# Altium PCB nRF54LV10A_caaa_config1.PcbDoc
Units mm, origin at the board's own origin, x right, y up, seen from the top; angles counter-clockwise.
Board outline 10.2 x 7.5 mm, 6 copper layers (Top Layer, Mid-Layer 1, Mid-Layer 2, Mid-Layer 3, Mid-Layer 4, Bottom Layer), stack 1.59 mm thick; 21 components, 30 nets, 71 pads, 43 vias.
Unrouted connection lines stored in the file: 14.
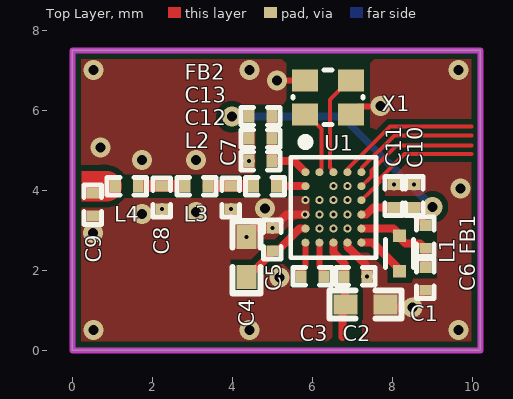
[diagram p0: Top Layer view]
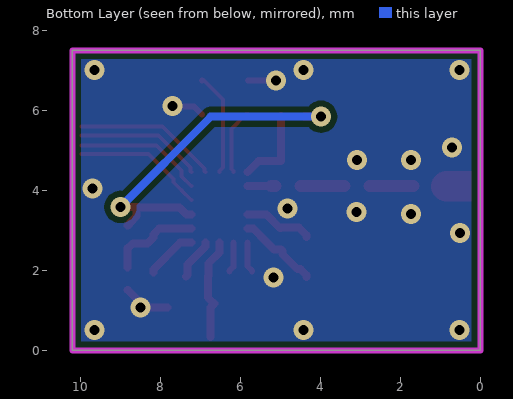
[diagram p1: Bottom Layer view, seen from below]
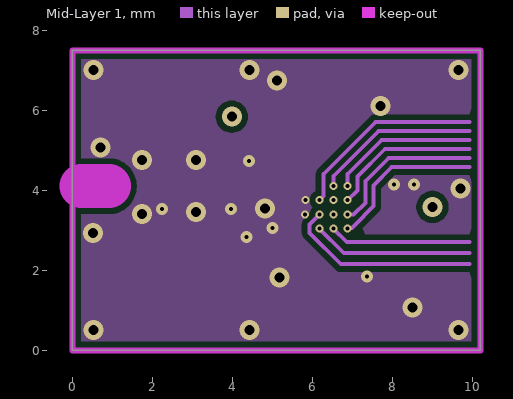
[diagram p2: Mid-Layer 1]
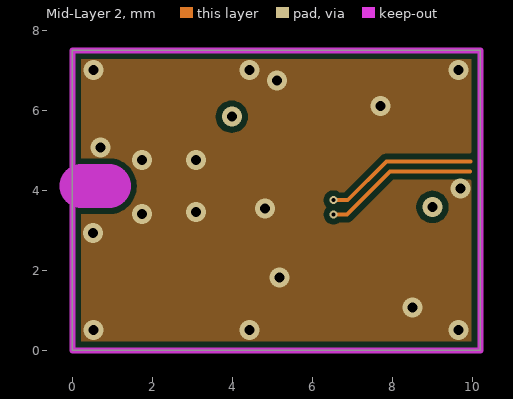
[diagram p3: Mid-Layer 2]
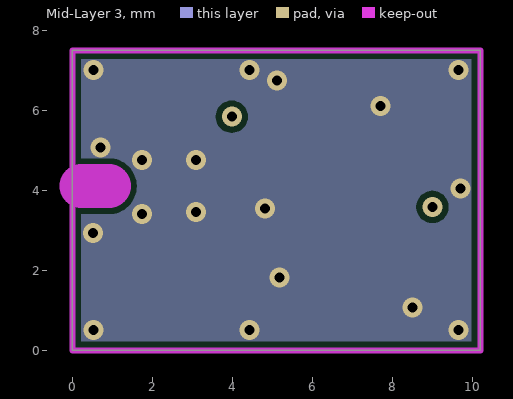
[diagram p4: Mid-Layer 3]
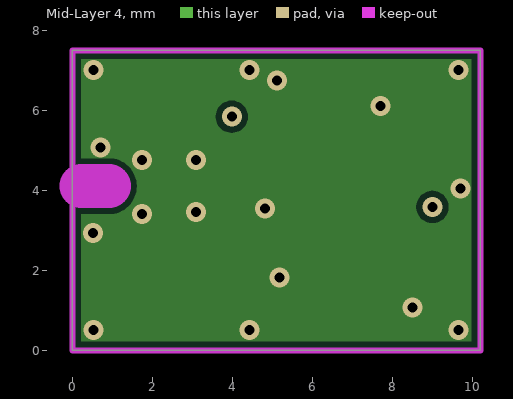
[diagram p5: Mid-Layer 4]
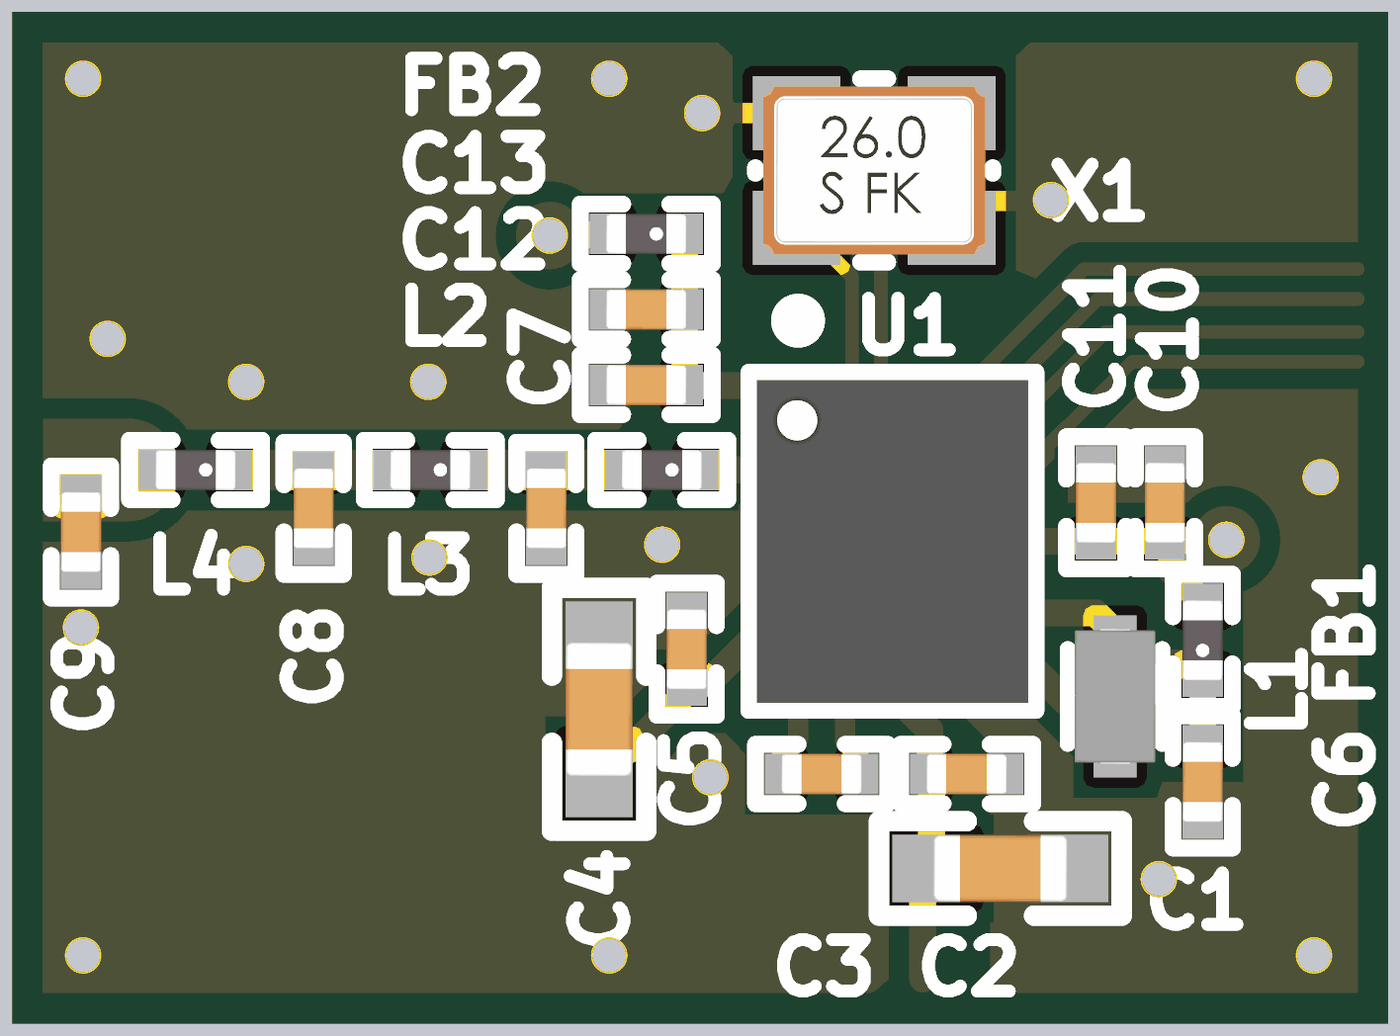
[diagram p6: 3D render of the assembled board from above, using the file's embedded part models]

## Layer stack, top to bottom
Top Solder: solder mask 0.0254, SM-003, Dk 4
Top Layer: signal copper 0.035
Dielectric 1: prepreg 0.07, Dk 4.2
Mid-Layer 1: signal copper 0.035
Dielectric 4: prepreg 0.07, PP-006, Dk 4.1
Mid-Layer 2: signal copper 0.035
Dielectric 3: core 1.1, Dk 4.6
Mid-Layer 3: signal copper 0.035
Dielectric 5: prepreg 0.07, PP-006, Dk 4.1
Mid-Layer 4: signal copper 0.035
Dielectric 2: prepreg 0.07, Dk 4.2
Bottom Layer: signal copper 0.035
Board Layer Stack Bottom Solder: solder mask 0.0254, SM-003, Dk 4

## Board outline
0,0 0,7.5 10.2,7.5 10.2,0

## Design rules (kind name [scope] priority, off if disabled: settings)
Clearance Polygon_RF [InNet('GND') vs InNet('RF')] p1: gap=0.15 ignorepadtopadclearanceinfootprint=FALSE
Clearance Clearance_Poly [(InNamedPolygon('Top_Layer-GND')) or (InNamedPolygon('Bottom_Layer-GND')) or (InNamedPolygon('Mid_Layer1-GND')) or (InNamedPolygon('Mid_Layer2-GND'))] p2: gap=0.15 ignorepadtopadclearanceinfootprint=FALSE
Clearance Clearance_nRF54 [WithinRoom('nRF54')] p3: gap=0.1 ignorepadtopadclearanceinfootprint=FALSE except(0: Arc-Hole Track-Hole SMDPad-Hole THPad-Hole Via-Hole Fill-Hole Poly-Hole Region-Hole Text-Hole; 0.15: Arc-Poly Arc-Region Track-Poly Track-Region SMDPad-Poly SMDPad-Region THPad-Poly THPad-Region Via-Poly Via-Region Fill-Poly Fill-Region Poly-Poly Poly-Region Region-Region)
Clearance [All] p4: gap=0.15 ignorepadtopadclearanceinfootprint=FALSE except(0: Arc-Hole Track-Hole SMDPad-Hole THPad-Hole Via-Hole Fill-Hole Poly-Hole Region-Hole Text-Hole)
ComponentClearance [All] p1 off: gap=0.254 collisioncheckmode=3 verticalgap=0.254 showdistances=FALSE
FabricationTestPointUsage TestPointUsage [All] p1: valid=0 allowmultiple=FALSE
FabricationTestpoint Testpoint [All] p1: side=3 testpointundercomponent=TRUE minsize=1.016 maxsize=2.54 preferedsize=1.524 minholesize=0 maxholesize=1.016 preferedholesize=0.813 testpointgrid=0.025 allowsidetop=TRUE allowsidebottom=TRUE usegrid=TRUE gridtolerance=0
Height [All] p1 off: minheight=0 maxheight=25.4 prefheight=12.7
HoleSize [All] p1: absolutevalues=TRUE maxlimit=4 minlimit=0.1 maxpercent=80.000 minpercent=20.000
HoleToHoleClearance [IsThruVia vs IsThruVia] p1: gap=0.36 allowstackedmicrovias=TRUE
MinimumAnnularRing [All] p1 off: minimumring=0.152
PlaneClearance [All] p1: clearance=0.2
PolygonConnect Component_direct [InComponent('C1') or InComponent('C2') or InComponent('C4')  or InComponent('C5') or InComponent('C6') or InComponent('C7') or InComponent('C8') or InComponent('C9') or InComponent('C10') or InComponent('C11') or InComponent('C12') or InComponent('C13') or InComponent('L4')   or InComponent('U1')] p1: connectstyle=Direct reliefconductorwidth=0.254 reliefentries=4 polygonreliefangle="90 Angle" airgapwidth=0.254
PolygonConnect "Via GND" [isVia and innet('GND')] p2: connectstyle=Direct reliefconductorwidth=0.254 reliefentries=4 polygonreliefangle="90 Angle" airgapwidth=0.254
PolygonConnect [All] p3: thpad.connectstyle=Relief thpad.reliefconductorwidth=0.254 thpad.reliefentries=4 thpad.polygonreliefangle="90 Angle" thpad.airgapwidth=0.15 smdpad.connectstyle=Relief smdpad.reliefconductorwidth=0.25 smdpad.reliefentries=4 smdpad.polygonreliefangle="90 Angle" smdpad.airgapwidth=0.15 via.connectstyle=Direct via.reliefconductorwidth=0.254 via.reliefentries=4 via.polygonreliefangle="90 Angle" via.airgapwidth=0.25
RoomDefinition nRF54 [False vs False] p1: confinementstyle=ConfineIn formatcopy=TRUE lockcomponents=FALSE outline 5.334,5.95 10.1,5.95 10.1,1.975 5.334,1.975
RoutingVias [All] p1: holewidth=0.2 width=0.4 viastyle="Through Hole" minholewidth=0.1 minwidth=0.2 maxholewidth=1 maxwidth=2 useviatemplates=TRUE viatemplateguid#1={5C31B0A3-9274-4A8C-AAD4-E2B2741298D6} viatemplateguid#2={C8464F81-CA02-4378-B3B7-72CF0372187D} viatemplatename#1=v20h10m0 viatemplatename#2=v30h10m0
SilkToSolderMaskClearance SilkscreenOverComponentPads [IsPad] p1: minsilkscreentomaskgap=0.254 clearancetoexposedcopper=TRUE
SolderMaskExpansion SolderMaskExpansion_via [IsVia] p1: expansion=0.102 istentingtop=TRUE
SolderMaskExpansion [All] p2: expansion=0.076 istentingtop=FALSE
Width [All] p1: maxlimit=3 minlimit=0.09 preferedwidth=0.15
22 further rules are at their usual default settings.

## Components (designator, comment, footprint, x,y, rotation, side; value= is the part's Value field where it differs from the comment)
C1 "10µF" CAPC1005X04L 7.325,1.15 r180 top
C2 "100nF" CAPC0603X03L_C#1 7.075,1.85 r0 top
C3 "1.0µF" CAPC0603X03L_C#2 6,1.85 r180 top
C4 "10µF" CAPC1005X04L 4.35,2.33 r270 top
C5 "100nF" CAPC0603X03L_C#1 5,2.775 r90 top
C6 "4.7µF" CAPC0603X03L_C#3 8.825,1.791 r90 top
C7 "1.2pF" CAPC0603X03L_C#3 3.959,3.82 r90 top
C8 "0.8pF" CAPC0603X03L_C#3 2.234,3.82 r90 top
C9 "0.3pF" CAPC0603X03L_C#3 0.509,3.644 r90 top
C10 "2.2µF" CAPC0603X03L_C#1 8.545,3.861 r90 top
C11 "10nF" CAPC0603X03L_C#3 8.035,3.861 r270 top
C12 "18pF" CAPC0603X03L_C#3 4.7,4.735 r0 top
C13 "2.2µF" CAPC0603X03L_C#1 4.7,5.295 r180 top
FB1 "120R/0.2A" INDC0603X03L_C 8.825,2.841 r90 top
FB2 "120R/0.2A" INDC0603X03L_C 4.7,5.855 r180 top
L1 "4.7µH" INDDFN10X06X08L31X32L 8.175,2.425 r270 top
L2 "2.7nH" INDC0603X03L_C 4.815,4.105 r180 top
L3 "6.2nH" INDC0603X03L_C 3.099,4.105 r180 top
L4 "4.3nH" INDC0603X03L_C 1.359,4.105 r180 top
U1 "nRF54LV10A-CAAA" BGA29CP35_5X6_239X201X45B20 6.525,3.575 r0 top
X1 "32MHz" BT-XTAL_1612 6.389,6.325 r0 top

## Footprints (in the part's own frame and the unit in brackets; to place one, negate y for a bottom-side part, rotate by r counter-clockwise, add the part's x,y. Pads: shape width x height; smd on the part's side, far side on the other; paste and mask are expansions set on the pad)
BGA29CP35_5X6_239X201X45B20 [mm] "Ball Grid Array (BGA) Collapsing, 0.35 mm pitch, rect.; 29 pin, 2.393 mm L X 2.012 mm W X 0.45 mm H body"
  round 0.2 smd paste+0 mask+0.025: A1(-0.7,0.88) A2(-0.35,0.88) A3(0,0.88) A4(0.35,0.88) A5(0.7,0.88) B1(-0.7,0.53) B3(0,0.53) B4(0.35,0.53) B5(0.7,0.53) C1(-0.7,0.18) C2(-0.35,0.18) C3(0,0.18) C4(0.35,0.18) C5(0.7,0.18) D1(-0.7,-0.18) D2(-0.35,-0.18) D3(0,-0.18) D4(0.35,-0.18) D5(0.7,-0.18) E1(-0.7,-0.53) E2(-0.35,-0.53) E3(0,-0.53) E4(0.35,-0.53) E5(0.7,-0.53) F1(-0.7,-0.88) F2(-0.35,-0.88) F3(0,-0.88) F4(0.35,-0.88) F5(0.7,-0.88)
  silkscreen extent -1.07,-1.26 1.07,1.74, body extent -1.01,-1.2 1.01,1.2, height 0.45
BT-XTAL_1612 [mm] "Crystal 1.6 x 1.2 mm"
  rect 0.65x0.55 smd: 1(-0.575,-0.425) 2(0.575,-0.425) 3(0.575,0.425) 4(-0.575,0.425)
  silkscreen extent -0.88,-0.68 0.88,0.68, body extent -0.83,-0.63 0.83,0.63, height 0.41
CAPC0603X03L_C#1 [mm] "Chip Capacitor, 2-Leads, Body 0.6x0.3mm, IPC High Density"
  rect 0.27x0.3 smd mask+0.05: 1(-0.285,0)
  rect 0.27x0.3 smd mask+0: 2(0.285,0)
  silkscreen extent -0.49,-0.22 0.49,0.22, body extent -0.3,-0.15 0.3,0.15, height 0.3
CAPC0603X03L_C#2 [mm] "Chip Capacitor, 2-Leads, Body 0.6x0.3mm, IPC High Density"
  rect 0.27x0.3 smd mask+0.05: 1(-0.285,0) 2(0.285,0)
  silkscreen extent -0.49,-0.22 0.49,0.22, body extent -0.3,-0.15 0.3,0.15, height 0.3
CAPC0603X03L_C#3 [mm] "Chip Capacitor, 2-Leads, Body 0.6x0.3mm, IPC High Density"
  rect 0.27x0.3 smd mask+0: 1(-0.285,0)
  rect 0.27x0.3 smd mask+0.05: 2(0.285,0)
  silkscreen extent -0.49,-0.22 0.49,0.22, body extent -0.3,-0.15 0.3,0.15, height 0.3
CAPC1005X04L [mm] "Chip Capacitor, 2-Leads, Body 1.0x0.5mm, IPC High Density"
  rect 0.6x0.5 smd mask+0: 1(-0.5,0)
  rect 0.6x0.5 smd: 2(0.5,0)
  silkscreen extent -0.9,-0.35 0.9,0.35, body extent -0.5,-0.25 0.5,0.25, height 0.5
INDC0603X03L_C [mm] "Chip Inductor, 2-Leads, Body 0.6x0.3mm, IPC High Density"
  rect 0.27x0.3 smd: 1(-0.285,0) 2(0.285,0)
  silkscreen extent -0.49,-0.22 0.49,0.22, body extent -0.3,-0.15 0.3,0.15, height 0.3
INDDFN10X06X08L31X32L [mm] "Inductor Dula Flat Package, 2-Leads, Body 1.0x0.6mm, IPC High Density"
  rect 0.31x0.32 smd mask+0.076: 1(-0.445,0) 2(0.445,0)
  silkscreen extent -0.35,-0.35 0.35,0.35, body extent -0.5,-0.3 0.5,0.3, height 0.79

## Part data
C1 C4: library part C0402-10µF-6.3V-X6S, "Capacitor, X6S, ±20%, 6.3V", Manufacturer=N.A., Part number NEMS=100200478
C2 C5: library part C0201-100n-10V-X7R, "Capacitor, X7R, ±10%, 100nF, 10V", Manufacturer=N.A., Part number NEMS=100200469
C3: library part C0201-1µ0-6.3V, "Capacitor, Ceramic, X5R, ±20%, 6.3V", Manufacturer=Murata, Manufacturer Part Number=GRM033R60J105MEA2D, Part number IPS=N.A., Part number NEMS=100200387, Supplier Part Number 1=490-7229-1-ND
C6: library part C0201-4.7µ-6V3-X5R-GRM035R60J475ME15J, "Capacitor, Ceramic, X5R, ±20%, 6.3V", Manufacturer=Murata, Manufacturer Part Number=GRM035R60J475ME15J, Part number IPS=N.A., Part number NEMS=100200685, Supplier Part Number 1=490-GRM035R60J475ME15JDKR-ND
C7: library part C0201-1.2p-HQ-Murata, "Capacitor, NP0, ±0.05pF, 50V", Manufacturer=Murata, Manufacturer Part Number=GJM0335C1H1R2WB01D, Part number IPS=N.A., Part number NEMS=100200457, Supplier Part Number 1=490-GJM0335C1H1R2WB01DCT-ND
C8: library part C0201-0.8p, "Capacitor, NP0, ±0.05pF, 50V", Manufacturer=Murata, Manufacturer Part Number=GJM0335C1HR80WB01, Part number IPS=80000001975, Part number NEMS=100200012, Part number Norautron=N.A.
C9: library part C0201-0.3p-50V-GRM0335C1HR30BA01, "Capacitor, C0G, ±0.1pF, 50V", Manufacturer=Murata, Manufacturer Part Number=GRM0335C1HR30BA01, Part number IPS=N.A., Part number NEMS=100200650, Supplier Part Number 1=490-6135-2-ND
C10 C13: library part C0201-2µ2-2.5V-X6T-GRM033D80E225ME47D, "Capacitor, Ceramic, 2.2µF 2.5V X6T 0201,±20%", Manufacturer=Murata, Manufacturer Part Number=GRM033D80E225ME47D, Part number IPS=N.A., Part number NEMS=100200527, Supplier Part Number 1=81-GRM033D80E225ME7D
C11: library part C0201-10n-6.3V-X7R, "Capacitor, X7R, 6.3V", Manufacturer=Murata, Manufacturer Part Number=GRM033R70J103KA01D, Part number IPS=N.A., Part number NEMS=100200407, Supplier Part Number 1=490-1262-1-ND
C12: library part C0201-18p, "Capacitor, C0G, ±5%, 25V", Manufacturer="Walsin Technology Corporation", Manufacturer Part Number=0201N180J250CT, Part number IPS=00000000862, Part number NEMS=100200035, Part number Norautron=26207023, Supplier Part Number 1=N.A.
FB1 FB2: library part FB0201-120R@100M-200mA-BLM03AG121SN1D, "Ferrite Bead, 120 Ohm @ 100MHz, 200mA, 500 mOhm Max", Manufacturer=Murata, Manufacturer Part Number=BLM03AG121SN1D, Part number IPS=N.A., Part number NEMS=100300419, Supplier Part Number 1=490-5622-1-ND
L1: library part L0402-4µ7-PLEA67BCA4R7M-1PT00, "Inductor, 300mA, ±20%, 1.08R", Manufacturer="TDK Corporation", Manufacturer Part Number=PLEA67BCA4R7M-1PT00, Part number IPS=N.A., Part number NEMS=100300441, Supplier Part Number 1=445-PLEA67BCA4R7M-1PT00TR-ND
L2: library part L0201-2n7-HQ-Murata, "Inductor, 600mA, ±0.1ｎH, 120mOhm", Manufacturer=Murata, Manufacturer Part Number=LQP03HQ2N7B02, Part number IPS=00000001753, Part number NEMS=100300214, Part number Norautron=N.A., Supplier Part Number 1=490-13909-1-ND
L3: library part L0201-6n2-HQ-Murata, "Inductor, 400mA, ±3%, 250mOhm", Manufacturer=Murata, Manufacturer Part Number=LQP03HQ6N2H02, Part number IPS=N.A., Part number NEMS=100300237, Supplier Part Number 1=490-13949-1-ND
L4: library part L0201-4n3-HQ-Murata, "Inductor, 500mA, ±3%, 170mOhm", Manufacturer=Murata, Manufacturer Part Number=LQP03HQ4N3H02, Part number IPS=N.A., Part number NEMS=100300230, Supplier Part Number 1=490-13941-1-ND
U1: "Multi-protocol Bluetooth Low Energy, IEEE 802.15.4 and 2.4GHz proprietary Wireless MCU", Manufacturer="Nordic Semiconductor", Part number IPS=N.A., Part number NEMS=102000317
X1: library part XTAL_SMD1612_32MHz_8pF_Kyocera, "XTAL SMD 1612, 32MHz, Cl=8pF, Tot: ±40ppm, Aging: ±1ppm/year", Manufacturer=Kyocera, Manufacturer Part Number=CX1612DB32000D0WZRC3, Part number IPS=N.A., Part number NEMS=101600029

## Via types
v1: diameter 0.5, hole 0.25, Top Layer to Bottom Layer, tented both sides, 20 vias
v2: diameter 0.2, hole 0.1, Top Layer to Mid-Layer 1, tented top, 13 vias
v3: diameter 0.3, hole 0.1, Top Layer to Mid-Layer 1, tented top, 8 vias
v4: diameter 0.2, hole 0.1, Mid-Layer 1 to Mid-Layer 2, tented top, 2 vias

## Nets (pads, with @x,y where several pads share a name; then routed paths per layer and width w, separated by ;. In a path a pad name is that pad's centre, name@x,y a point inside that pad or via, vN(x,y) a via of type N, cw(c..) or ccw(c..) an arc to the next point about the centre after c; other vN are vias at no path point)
ANT: L2.1 U1.B1 | length 0.8
  Top Layer w0.2: L2.1@5.13,4.105 U1.B1
  Top Layer w0.3: L2.1@5.125,4.105 L2.1@5.23,4.105
DCC: L1.2 U1.F5 | length 1.3
  Top Layer w0.2: U1.F5 7.505,2.695 8.175,2.025 8.175,1.975 L1.2@8.175,1.95
DECA: C10.1 C11.2 FB1.2 FB2.2 U1.D5 | length 8.8
  Top Layer w0.2: v1@3.99,5.849 FB2.2@4.409,5.849 ; U1.D5 7.345,3.395 7.526,3.576 C10.1 8.567,3.555 8.582,3.555 8.595,3.541 8.595,3.356 8.775,3.176 8.775,3.161 8.81,3.126 FB1.2 ; C10.1@8.565,3.566 8.55,3.581 8.995,3.581 v1(9,3.586)
  Bottom Layer w0.2: v1(3.984,5.843) 6.743,5.843 v1(9,3.586)
DECD: C6.2 FB1.1 L1.1 U1.E5 | length 2.3
  Top Layer w0.2: U1.E5 8.03,3.045 8.175,2.9 8.175,2.825 8.325,2.675 8.691,2.675 8.81,2.556 8.825,2.556 C6.2@8.825,2.076
GND: C1.1 C2.2 C4.1 C5.2 C6.1 C7.1 C8.1 C9.1 C10.2 C11.1 C12.1 C13.2 U1.C1 U1.D1 U1.F4 X1.2 X1.4 | length 5.6
  Top Layer w0.15: v1(5.114,6.75) X1.4 ; X1.2 7.164,6.1 7.695,6.1 v1(7.7,6.105)
  Top Layer w0.2: v3(4.35,2.83) 4.35,2.88 4.537,3.067 C5.2@4.993,3.067 ; v3(5,3.06) 5.015,3.06 5.35,3.395 U1.D1 U1.D1@5.827,3.397 ; U1.F4 6.875,2.6 7.325,2.15 7.325,2.017 7.325,1.975 7.325,1.885 v3(7.36,1.85) ; C1.1@7.825,1.075 7.827,1.072 8.498,1.072 v1(8.5,1.07) 8.557,1.127 8.557,1.253 8.81,1.506 C6.1
  other v1: 0.525,0.505 4.425,0.505 9.65,0.505 5.175,1.825 0.509,2.936 1.734,3.408 3.093,3.455 4.818,3.55 9.7,4.05 1.734,4.758 3.084,4.758 0.707,5.077 0.525,7.005 4.425,7.005 9.65,7.005
  other v2: 5.81,3.395 5.825,3.755
  other v3: 2.234,3.535 3.959,3.535 8.035,4.146 8.545,4.146 4.415,4.735
NetC3_1: C3.1 U1.F2 | length 0.8
  Top Layer w0.15: U1.F2 6.175,2.09 6.275,1.99 C3.1@6.275,1.975
NetC3_2: C3.2 U1.F1 | length 0.8
  Top Layer w0.15: C3.2@5.705,1.975 5.705,1.99 5.825,2.11 U1.F1
NetC4_2: C4.2 C5.1 U1.E1 | length 2.1
  Top Layer w0.2: C4.2 4.35,1.88 4.5,2.03 4.575,2.03 4.95,2.405 4.95,2.49 4.985,2.525 5.16,2.525 5.334,2.699 5.68,3.045 U1.E1
NetC7_2: C7.2 L2.2 L3.1 | length 1.1
  Top Layer w0.3: L3.1@3.399,4.105 C7.2 L2.2@4.5,4.105
NetC8_2: C8.2 L3.2 L4.1 | length 1.1
  Top Layer w0.3: L4.1@1.674,4.105 L3.2@2.775,4.105
NetC12_2: C12.2 C13.1 FB2.1 U1.A1 | length 2
  Top Layer w0.2: C12.2 FB2.1 ; C12.2@5.06,4.73 5.55,4.73 U1.A1
NRESET: U1.C2 | length 4.9
  Mid-Layer 1 w0.1: v2(6.175,3.755) 6.175,3.764 6.275,3.864 6.275,4.405 7.575,5.705 7.975,5.705 9.925,5.705
P1.00/AIN0: U1.E3 | length 3.5
  Mid-Layer 1 w0.1: v2(6.525,3.045) 6.525,3.041 6.861,2.705 7.975,2.705 9.925,2.705
P1.01/AIN1: U1.C3 | length 3.8
  Mid-Layer 2 w0.1: v4(6.525,3.755) 6.879,3.755 7.848,4.724 9.947,4.724
  other v2: 6.525,3.755
P1.02/AIN2: U1.D3 | length 3.9
  Mid-Layer 2 w0.1: v2(6.525,3.395) 6.86,3.395 7.937,4.472 9.945,4.472
  other v4: 6.525,3.395
P1.03/AIN3: U1.A4 | length 3.6
  Top Layer w0.1: U1.A4 6.894,4.474 6.894,4.544 7.944,5.594 9.975,5.594
P1.05: U1.B4 | length 3.7
  Mid-Layer 1 w0.1: v2(6.875,4.105) 6.875,4.405 7.725,5.255 9.925,5.255
P1.07/AIN4: U1.C4 | length 3.8
  Mid-Layer 1 w0.1: v2(6.875,3.755) 6.879,3.755 7.125,4.001 7.125,4.347 7.808,5.03 9.925,5.03
P1.09: U1.B3 | length 4.1
  Mid-Layer 1 w0.1: v2(6.525,4.105) 6.525,4.355 7.65,5.48 9.925,5.48
P1.10/AIN5: U1.A5 | length 3.2
  Top Layer w0.1: U1.A5 7.244,4.474 7.244,4.569 8.047,5.372 9.975,5.372
P1.11/AIN6: U1.D4 | length 4
  Mid-Layer 1 w0.1: v2(6.875,3.395) 7.032,3.395 7.325,3.688 7.325,4.23 7.9,4.805 9.925,4.805
P1.12/AIN7: U1.E4 | length 4
  Mid-Layer 1 w0.1: v2(6.875,3.045) 6.894,3.064 6.984,3.064 7.049,3.129 7.525,3.606 7.525,4.125 7.98,4.58 9.925,4.58
P1.13/XL1: U1.B5 | length 3.3
  Top Layer w0.1: U1.B5 7.229,4.105 7.475,4.351 7.475,4.5 8.103,5.128 9.975,5.128
P1.14/XL2: U1.C5 | length 3.3
  Top Layer w0.1: U1.C5 7.229,3.755 7.475,4.001 7.475,4.005 7.675,4.205 7.675,4.283 7.823,4.431 7.826,4.431 8.302,4.907 9.975,4.907
RF: C9.2 L4.2 | length 0.2
  Top Layer w0.762: 0.7,4.105 0.857,4.105
SWDCLK: U1.D2 | length 4.9
  Mid-Layer 1 w0.1: v2(6.175,3.395) 6.171,3.395 5.925,3.149 5.925,2.941 6.711,2.155 7.975,2.155 9.925,2.155
SWDIO: U1.E2 | length 4
  Mid-Layer 1 w0.1: v2(6.175,3.045) 6.175,3.041 6.786,2.43 7.975,2.43 9.925,2.43
VDDL:nRF: C1.2 C2.1 U1.F3 | length 2.6
  Top Layer w0.2: U1.F3 6.525,2.45 6.803,2.172 6.803,1.862 6.815,1.85 6.815,1.325 6.665,1.175 6.65,1.175 6.75,1.075 6.75,0.33
XC1: U1.A2 X1.1 | length 1.7
  Top Layer w0.1: X1.1 5.864,5.9 5.884,5.88 6.225,5.539 6.225,4.532 6.175,4.482 U1.A2
XC2: U1.A3 X1.3 | length 2.6
  Top Layer w0.1: U1.A3 6.525,4.482 6.439,4.568 6.439,5.88 6.439,6.258 6.45,6.269 6.45,6.286 6.914,6.75 X1.3

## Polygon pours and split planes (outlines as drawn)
GND on Bottom Layer "Bottom_Layer-GND" (solid, remove dead copper, pour order 15): 0,0.005 10.2,0.005 10.2,7.48 0,7.48
GND on Mid-Layer 4 "Mid_Layer2-GND" (solid, remove dead copper, pour order 12): 0,0.005 10.2,0.005 10.2,7.48 0,7.48
GND on Top Layer "Top_Layer-GND" (solid, remove dead copper, pour order 14): 0,0.005 10.2,0.005 10.2,7.48 0,7.48
GND on Mid-Layer 2 "Mid_Layer1-GND" (solid, remove dead copper, pour order 10): 0,0.005 10.2,0.005 10.2,7.48 0,7.48
GND on Mid-Layer 3 "Mid_Layer1-GND" (solid, remove dead copper, pour order 16): 0,0.005 10.2,0.005 10.2,7.48 0,7.48
GND on Mid-Layer 1 "Mid_Layer1-GND" (solid, remove dead copper, pour order 17): 0,0.005 10.2,0.005 10.2,7.48 0,7.48

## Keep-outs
Mid-Layer 1:
  lines w1.1: 0.226,4.105 0.916,4.105
Mid-Layer 4:
  lines w1.1: 0.226,4.105 0.916,4.105
Mid-Layer 2:
  lines w1.1: 0.226,4.105 0.916,4.105
Mid-Layer 3:
  lines w1.1: 0.226,4.105 0.916,4.105
Keep-Out Layer:
  the board outline again, w0.15

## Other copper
Top Layer:
  region net RF: 0.7,4.486 0.226,4.486 0.226,3.724 0.7,3.724
  pour cut-out: 4.576,5.576 4.576,4.386 4.701,4.386 4.701,4.661 4.701,5.577
  pour cut-out: 5.925,3.85 5.925,3.325 6.05,3.325 6.05,3.6 6.05,3.85
  pour cut-out: 6.95,0.2 6.95,2.28 7.25,2.28 7.25,0.2
  pour cut-out: 5.663,2.155 5.663,2.605 5.537,2.605 5.537,2.405 4.862,2.405 4.862,2.155
  pour cut-out: 7.7,4.155 7.7,3.63 7.825,3.63 7.825,3.905 7.825,4.155
  pour cut-out: 5.339,7.175 7.439,7.175 7.439,5.475 5.339,5.475

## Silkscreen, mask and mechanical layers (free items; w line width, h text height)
Mechanical 1:
  the board outline again, w0.15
